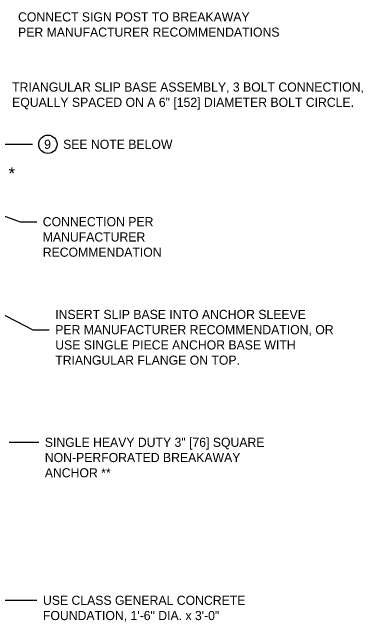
# Model space of a CAD drawing. Extents: x 49940 to 50043, y 49986 to 50011.
# Drawn here: x 50002.443 to 50004.745, y 49992.568 to 49996.567 of the extents above; entities that cross this region are included whole.
import ezdxf

# ---------------------------------------------------------------- set-up
doc = ezdxf.new("R2010")
doc.units = 0
doc.layers.add('Level 2', color=7, linetype='Continuous')
doc.layers.add('Level 3', color=7, linetype='Continuous')

msp = doc.modelspace()

# ---------------------------------------------------------------- linework, layer by layer
at = {"layer": 'Level 2'}
msp.add_circle((50002.6777, 49995.7004), 0.06, dxfattribs=at)
at = {"layer": 'Level 3'}
for p, q in [((50001.9563, 49995.7004), (50002.5777, 49995.7004)), ((50001.8324, 49995.426), (50002.496, 49995.1926)), ((50002.496, 49995.1926), (50002.6042, 49995.1926)), ((50001.7207, 49994.9234), (50002.5779, 49994.4842)), ((50002.5779, 49994.4842), (50002.6861, 49994.4842)), ((50002.4245, 49993.7454), (50002.6177, 49993.7454)), ((50002.3564, 49992.7088), (50002.6055, 49992.7088))]:
    msp.add_line(p, q, dxfattribs=at)

# ---------------------------------------------------------------- texts
at = {"layer": 'Level 2'}
for s, p in [('CONNECT SIGN POST TO BREAKAWAY ', (50002.482, 49996.5062)), ('PER MANUFACTURER RECOMMENDATIONS', (50002.482, 49996.4062)), ('TRIANGULAR SLIP BASE ASSEMBLY, 3 BOLT CONNECTION, ', (50002.443, 49996.0459)), ('EQUALLY SPACED ON A 6" [152] DIAMETER BOLT CIRCLE. ', (50002.443, 49995.9459)), ('9', (50002.6532, 49995.6704)), ('SEE NOTE BELOW', (50002.7777, 49995.6704)), ('CONNECTION PER ', (50002.6442, 49995.1626)), ('MANUFACTURER ', (50002.6442, 49995.0626)), ('RECOMMENDATION', (50002.6442, 49994.9626)), ('INSERT SLIP BASE INTO ANCHOR SLEEVE ', (50002.7261, 49994.5542)), ('PER MANUFACTURER RECOMMENDATION, OR ', (50002.7261, 49994.4542)), ('USE SINGLE PIECE ANCHOR BASE WITH ', (50002.7261, 49994.3542)), ('TRIANGULAR FLANGE ON TOP.', (50002.7261, 49994.2542)), ('SINGLE HEAVY DUTY 3" [76] SQUARE', (50002.6577, 49993.7154)), ('NON-PERFORATED BREAKAWAY', (50002.6577, 49993.6154)), ('ANCHOR **', (50002.6577, 49993.5154)), ('USE CLASS GENERAL CONCRETE', (50002.6455, 49992.6788)), ('FOUNDATION, 1\'-6" DIA. x 3\'-0"', (50002.6455, 49992.5788))]:
    msp.add_text(s, height=0.06, dxfattribs=at).set_placement(p)
msp.add_text('*', height=0.08, rotation=359.5, dxfattribs=at).set_placement((50002.4194, 49995.4697))

doc.saveas('drawing.dxf')
